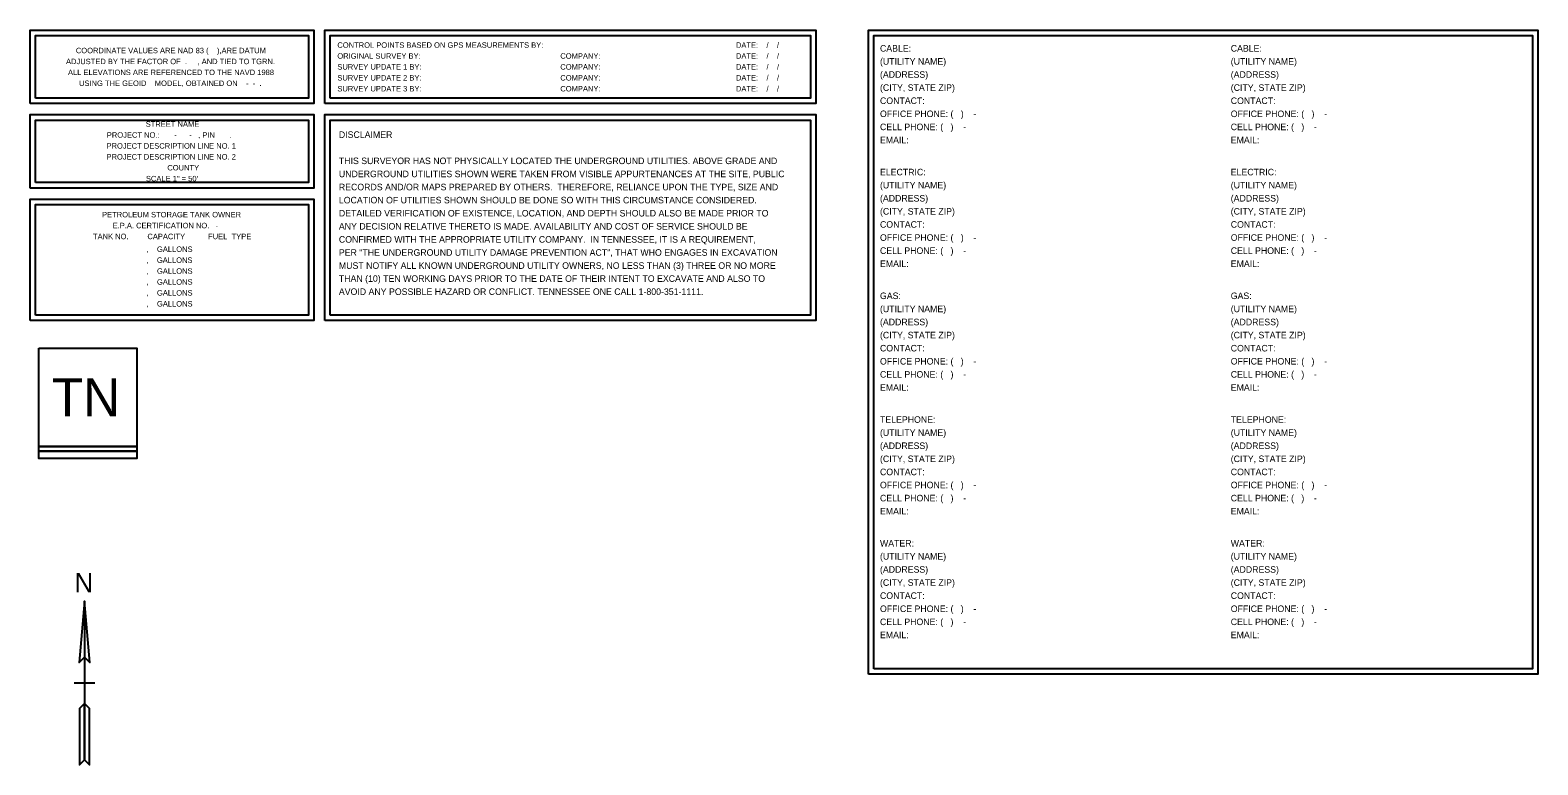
# Model space of a CAD drawing. Extents: x 1849512 to 1850893, y 666933 to 667606.
import ezdxf

# ---------------------------------------------------------------- set-up
doc = ezdxf.new("R2010")
doc.units = 0
for name, color, linetype in [('SUR - CTRL - Text', 7, 'Continuous'), ('SUR - Project Information and Notes', 7, 'Continuous'), ('SUR - UTL - Owners', 7, 'Continuous')]:
    doc.layers.add(name, color=color, linetype=linetype)

msp = doc.modelspace()

# ---------------------------------------------------------------- linework, layer by layer
at = {"layer": 'SUR - CTRL - Text'}
for points in [[(1849511.8, 667539), (1849511.8, 667606.4), (1849771.8, 667606.4), (1849771.8, 667539)], [(1849516.8, 667544), (1849516.8, 667601.4), (1849766.8, 667601.4), (1849766.8, 667544)], [(1849781.8, 667539), (1849781.8, 667606.4), (1850231.8, 667606.4), (1850231.8, 667539)], [(1849786.8, 667544), (1849786.8, 667601.4), (1850226.8, 667601.4), (1850226.8, 667544)]]:
    msp.add_lwpolyline(points, close=True, dxfattribs=at)
at = {"layer": 'SUR - Project Information and Notes'}
for p, q in [((1849561.5, 667008), (1849552.1, 667008)), ((1849571, 667008), (1849561.5, 667008))]:
    msp.add_line(p, q, dxfattribs=at)
for points in [[(1849511.8, 667461.6), (1849511.8, 667529), (1849771.8, 667529), (1849771.8, 667461.6)], [(1849516.8, 667466.6), (1849516.8, 667524), (1849766.8, 667524), (1849766.8, 667466.6)], [(1849511.8, 667340.2), (1849511.8, 667451.6), (1849771.8, 667451.6), (1849771.8, 667340.2)], [(1849516.8, 667345.2), (1849516.8, 667446.6), (1849766.8, 667446.6), (1849766.8, 667345.2)], [(1849519.7, 667314.9), (1849609.7, 667314.9), (1849609.7, 667224.9), (1849519.7, 667224.9)], [(1849519.7, 667314.9), (1849609.7, 667314.9), (1849609.7, 667224.9), (1849519.7, 667224.9)], [(1849519.7, 667224.9), (1849609.7, 667224.9), (1849609.7, 667220.4), (1849519.7, 667220.4)], [(1849519.7, 667224.9), (1849609.7, 667224.9), (1849609.7, 667220.4), (1849519.7, 667220.4)], [(1849519.7, 667220.4), (1849609.7, 667220.4), (1849609.7, 667213.7), (1849519.7, 667213.7)], [(1849519.7, 667220.4), (1849609.7, 667220.4), (1849609.7, 667213.7), (1849519.7, 667213.7)], [(1849561.5, 667031.6), (1849566.4, 667026.7), (1849561.5, 667083)], [(1849557, 666933), (1849561.5, 666937.6), (1849561.5, 666989.3), (1849557, 666984.8)]]:
    msp.add_lwpolyline(points, close=True, dxfattribs=at)
msp.add_lwpolyline([(1849561.5, 667083), (1849556.6, 667026.7), (1849561.5, 667031.6), (1849566.4, 667026.7), (1849561.5, 667083), (1849561.5, 666937.6), (1849566.1, 666933), (1849566.1, 666984.8), (1849561.5, 666989.3), (1849557, 666984.8), (1849557, 666933), (1849561.5, 666937.6)], dxfattribs=at)
at = {"layer": 'SUR - UTL - Owners'}
for points in [[(1850280, 667016), (1850280, 667606.4), (1850893.3, 667606.4), (1850893.3, 667016)], [(1850285, 667021), (1850285, 667601.4), (1850888.3, 667601.4), (1850888.3, 667021)], [(1849781.8, 667340.2), (1849781.8, 667529), (1850231.8, 667529), (1850231.8, 667340.2)], [(1849786.8, 667345.2), (1849786.8, 667524), (1850226.8, 667524), (1850226.8, 667345.2)]]:
    msp.add_lwpolyline(points, close=True, dxfattribs=at)

# ---------------------------------------------------------------- texts
at = {"layer": 'SUR - CTRL - Text'}
for s, p in [('COORDINATE VALUES ARE NAD 83 (    ),ARE DATUM', (1849553.7, 667585.2)), ('CONTROL POINTS BASED ON GPS MEASUREMENTS BY:                                            ', (1849793.3, 667590.2)), ('ORIGINAL SURVEY BY:                               ', (1849793.3, 667580.2)), ('COMPANY:                               ', (1849997.6, 667580.2)), ('DATE:    /    /   ', (1850158.5, 667590.2)), ('DATE:    /    /    ', (1850158.5, 667580.2)), ('ADJUSTED BY THE FACTOR OF  .     , AND TIED TO TGRN. ', (1849544.7, 667575.2)), ('ALL ELEVATIONS ARE REFERENCED TO THE NAVD 1988', (1849546.5, 667565.2)), ('SURVEY UPDATE 1 BY:                               ', (1849793.3, 667570.2)), ('COMPANY:                               ', (1849997.6, 667570.2)), ('DATE:    /    /     ', (1850158.5, 667570.2)), ('USING THE GEOID    MODEL, OBTAINED ON    -  -  .', (1849556.6, 667555.2)), ('SURVEY UPDATE 2 BY:                               ', (1849793.3, 667560.2)), ('COMPANY:                               ', (1849997.6, 667560.2)), ('DATE:    /    /     ', (1850158.5, 667560.2)), ('SURVEY UPDATE 3 BY:                               ', (1849793.3, 667550.2)), ('COMPANY:                               ', (1849997.6, 667550.2)), ('DATE:    /    /    ', (1850158.5, 667550.2))]:
    msp.add_text(s, height=5, dxfattribs=at).set_placement(p)
at = {"layer": 'SUR - Project Information and Notes'}
for s, height, p in [('            STREET NAME           ', 5, (1849594.7, 667517.8)), ('  PROJECT DESCRIPTION LINE NO. 1  ', 5, (1849578, 667497.8)), ('PROJECT NO.:       -      -   , PIN       .  ', 5, (1849582.1, 667507.8)), ('  PROJECT DESCRIPTION LINE NO. 2  ', 5, (1849578, 667487.8)), ('           COUNTY', 5, (1849616.4, 667477.8)), ('SCALE 1" = 50\'', 5, (1849617.9, 667467.8)), (' PETROLEUM STORAGE TANK OWNER ', 5, (1849575.8, 667434.8)), ('TANK NO.         CAPACITY           FUEL  TYPE', 5, (1849569.4, 667414.8)), ('E.P.A. CERTIFICATION NO.   -      ', 5, (1849587.4, 667424.8)), ('  ,    GALLONS', 5, (1849614.6, 667403.1)), ('   ,    GALLONS', 5, (1849612.6, 667393.1)), ('  ,    GALLONS', 5, (1849614.6, 667383.1)), ('  ,    GALLONS', 5, (1849614.6, 667373.1)), ('  ,    GALLONS', 5, (1849614.6, 667363.1)), ('  ,    GALLONS', 5, (1849614.6, 667353.1)), ('TN', 35, (1849531.8, 667252.4)), ('N', 17.7, (1849552.5, 667091.1))]:
    msp.add_text(s, height=height, dxfattribs=at).set_placement(p)
at = {"layer": 'SUR - UTL - Owners'}
for s, p in [('CABLE:', (1850290.5, 667586.7)), ('CABLE:', (1850611.9, 667586.7)), ('(UTILITY NAME)                                    ', (1850290.5, 667574.7)), ('(UTILITY NAME)                                    ', (1850611.9, 667574.7)), ('(ADDRESS)                                               ', (1850290.5, 667562.7)), ('(CITY, STATE ZIP)                                 ', (1850290.5, 667550.7)), ('(ADDRESS)                                               ', (1850611.9, 667562.7)), ('(CITY, STATE ZIP)                                 ', (1850611.9, 667550.7)), ('CONTACT:                                                   ', (1850290.5, 667538.7)), ('CONTACT:                                                   ', (1850611.9, 667538.7)), ('OFFICE PHONE: (   )    -    ', (1850290.5, 667526.7)), ('OFFICE PHONE: (   )    -    ', (1850611.9, 667526.7)), ('CELL PHONE: (   )    -    ', (1850290.5, 667514.7)), ('CELL PHONE: (   )    -    ', (1850611.9, 667514.7)), ('DISCLAIMER', (1849794.7, 667507.6)), ('EMAIL:                                                    ', (1850290.5, 667502.7)), ('EMAIL:                                                    ', (1850611.9, 667502.7)), ('THIS SURVEYOR HAS NOT PHYSICALLY LOCATED THE UNDERGROUND UTILITIES. ABOVE GRADE AND ', (1849794.7, 667483.6)), ('UNDERGROUND UTILITIES SHOWN WERE TAKEN FROM VISIBLE APPURTENANCES AT THE SITE, PUBLIC ', (1849794.7, 667471.6)), ('ELECTRIC:', (1850290.5, 667473.3)), ('ELECTRIC:', (1850611.9, 667473.3)), ('RECORDS AND/OR MAPS PREPARED BY OTHERS.  THEREFORE, RELIANCE UPON THE TYPE, SIZE AND ', (1849794.7, 667459.6)), ('(UTILITY NAME)                                    ', (1850290.5, 667461.3)), ('(UTILITY NAME)                                    ', (1850611.9, 667461.3)), ('LOCATION OF UTILITIES SHOWN SHOULD BE DONE SO WITH THIS CIRCUMSTANCE CONSIDERED.', (1849794.7, 667447.6)), ('(ADDRESS)                                         ', (1850290.5, 667449.3)), ('(ADDRESS)                                         ', (1850611.9, 667449.3)), ('DETAILED VERIFICATION OF EXISTENCE, LOCATION, AND DEPTH SHOULD ALSO BE MADE PRIOR TO ', (1849794.7, 667435.6)), ('(CITY, STATE ZIP)                                 ', (1850290.5, 667437.3)), ('(CITY, STATE ZIP)                                 ', (1850611.9, 667437.3)), ('ANY DECISION RELATIVE THERETO IS MADE. AVAILABILITY AND COST OF SERVICE SHOULD BE ', (1849794.7, 667423.6)), ('CONFIRMED WITH THE APPROPRIATE UTILITY COMPANY.  IN TENNESSEE, IT IS A REQUIREMENT, ', (1849794.7, 667411.6)), ('OFFICE PHONE: (   )    -    ', (1850290.5, 667413.3)), ('CONTACT:                                                   ', (1850290.5, 667425.3)), ('OFFICE PHONE: (   )    -    ', (1850611.9, 667413.3)), ('CONTACT:                                                   ', (1850611.9, 667425.3)), ('PER "THE UNDERGROUND UTILITY DAMAGE PREVENTION ACT", THAT WHO ENGAGES IN EXCAVATION ', (1849794.7, 667399.6)), ('CELL PHONE: (   )    -    ', (1850290.5, 667401.3)), ('CELL PHONE: (   )    -    ', (1850611.9, 667401.3)), ('MUST NOTIFY ALL KNOWN UNDERGROUND UTILITY OWNERS, NO LESS THAN (3) THREE OR NO MORE ', (1849794.7, 667387.6)), ('EMAIL:                                                    ', (1850290.5, 667389.3)), ('EMAIL:                                                    ', (1850611.9, 667389.3)), ('THAN (10) TEN WORKING DAYS PRIOR TO THE DATE OF THEIR INTENT TO EXCAVATE AND ALSO TO ', (1849794.7, 667375.7)), ('AVOID ANY POSSIBLE HAZARD OR CONFLICT. TENNESSEE ONE CALL 1-800-351-1111.', (1849794.7, 667363.7)), ('GAS:', (1850290.5, 667359.9)), ('GAS:', (1850611.9, 667359.9)), ('(UTILITY NAME)                                    ', (1850290.5, 667347.9)), ('(UTILITY NAME)                                    ', (1850611.9, 667347.9)), ('(ADDRESS)                                         ', (1850290.5, 667335.9)), ('(ADDRESS)                                         ', (1850611.9, 667335.9)), ('(CITY, STATE ZIP)                                 ', (1850290.5, 667323.9)), ('(CITY, STATE ZIP)                                 ', (1850611.9, 667323.9)), ('CONTACT:                                                   ', (1850290.5, 667311.9)), ('CONTACT:                                                   ', (1850611.9, 667311.9)), ('OFFICE PHONE: (   )    -    ', (1850290.5, 667299.9)), ('CELL PHONE: (   )    -    ', (1850290.5, 667287.9)), ('OFFICE PHONE: (   )    -    ', (1850611.9, 667299.9)), ('CELL PHONE: (   )    -    ', (1850611.9, 667287.9)), ('EMAIL:                                                    ', (1850290.5, 667275.9)), ('EMAIL:                                                    ', (1850611.9, 667275.9)), ('TELEPHONE:', (1850290.5, 667246.5)), ('TELEPHONE:', (1850611.9, 667246.5)), ('(UTILITY NAME)                                    ', (1850290.5, 667234.5)), ('(UTILITY NAME)                                    ', (1850611.9, 667234.5)), ('(ADDRESS)                                         ', (1850290.5, 667222.5)), ('(ADDRESS)                                         ', (1850611.9, 667222.5)), ('(CITY, STATE ZIP)                                 ', (1850290.5, 667210.5)), ('(CITY, STATE ZIP)                                 ', (1850611.9, 667210.5)), ('CONTACT:                                                   ', (1850290.5, 667198.5)), ('CONTACT:                                                   ', (1850611.9, 667198.5)), ('OFFICE PHONE: (   )    -    ', (1850290.5, 667186.5)), ('OFFICE PHONE: (   )    -    ', (1850611.9, 667186.5)), ('CELL PHONE: (   )    -    ', (1850290.5, 667174.5)), ('CELL PHONE: (   )    -    ', (1850611.9, 667174.5)), ('EMAIL:                                                    ', (1850290.5, 667162.5)), ('EMAIL:                                                    ', (1850611.9, 667162.5)), ('WATER:', (1850290.5, 667133.1)), ('WATER:', (1850611.9, 667133.1)), ('(UTILITY NAME)                                    ', (1850290.5, 667121.1)), ('(ADDRESS)                                         ', (1850290.5, 667109.1)), ('(UTILITY NAME)                                    ', (1850611.9, 667121.1)), ('(ADDRESS)                                         ', (1850611.9, 667109.1)), ('(CITY, STATE ZIP)                                 ', (1850290.5, 667097.1)), ('(CITY, STATE ZIP)                                 ', (1850611.9, 667097.1)), ('CONTACT:                                                   ', (1850290.5, 667085.1)), ('CONTACT:                                                   ', (1850611.9, 667085.1)), ('OFFICE PHONE: (   )    -    ', (1850290.5, 667073.1)), ('OFFICE PHONE: (   )    -    ', (1850611.9, 667073.1)), ('CELL PHONE: (   )    -    ', (1850290.5, 667061.1)), ('CELL PHONE: (   )    -    ', (1850611.9, 667061.1)), ('EMAIL:                                                    ', (1850290.5, 667049.1)), ('EMAIL:                                                    ', (1850611.9, 667049.1))]:
    msp.add_text(s, height=6, dxfattribs=at).set_placement(p)

doc.saveas('drawing.dxf')
